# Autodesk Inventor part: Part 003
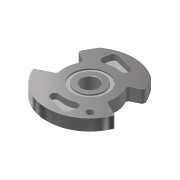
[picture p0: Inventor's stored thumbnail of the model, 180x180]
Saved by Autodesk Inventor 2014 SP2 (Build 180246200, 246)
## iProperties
Created: 2015-03
Part Number: Part 003
Material: Steel
Document SubType Name: Modeling
Designer: SFC
Density: 7.85 g/cm^3
Appearance: Steel
Mass: 161.859 g
Surface Area: 78.7289 cm^2
Volume: 20.6189 cm^3
Author: SFC
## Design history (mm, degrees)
sketch "Sketch1"
  geometry: L1 (-19, 25.997)-(-23.665, 17.917); L2 (-22.596, 14.42)-(-17.512, 11.94); L3 (19, 25.997)-(23.665, 17.917); L4 (22.596, 14.42)-(17.512, 11.94); L5 (0, -45.08)-(0, 45.08) reference; L6 (-29.187, -11.224)-(-19.581, -6.539); L7 (19.581, -6.539)-(29.187, -11.224); L8 (-49.656, 0)-(50.759, 0) reference; A1 r 32.2 centre (0, 0) between (-32.2, 0) and (-30.025, -11.633); A2 r 19 centre (0, 0) between (-16.637, 9.176) and (-18.509, -4.29); A3 r 2.5 centre (-21.5, 16.667) between (-23.665, 17.917) and (-22.596, 14.42); A4 r 2.5 centre (21.5, 16.667) between (22.596, 14.42) and (23.665, 17.917); A5 r 19 centre (0, 0) between (0, 19) and (-15.516, 10.967); A6 r 19 centre (0, 0) between (-18.089, -5.811) and (18.089, -5.811); A7 r 19 centre (0, 0) between (18.509, -4.29) and (16.637, 9.176); A8 r 19 centre (0, 0) between (15.516, 10.967) and (0, 19); A9 r 32.2 centre (0, 0) between (-19, 25.997) and (-32.2, 0); A10 r 32.2 centre (0, 0) between (-29.67, -12.511) and (29.67, -12.511); A11 r 32.2 centre (0, 0) between (30.025, -11.633) and (19, 25.997); A12 r 32.2 centre (0, 0) between (19, 25.997) and (-19, 25.997); A13 r 2 centre (-18.388, 10.142) between (-16.637, 9.176) and (-17.512, 11.94); A14 r 2 centre (-20.458, -4.741) between (-19.581, -6.539) and (-18.509, -4.29); A15 r 2 centre (18.388, 10.142) between (17.512, 11.94) and (16.637, 9.176); A16 r 2 centre (20.458, -4.741) between (18.509, -4.29) and (19.581, -6.539); A17 r 1 centre (-28.749, -12.123) between (-29.187, -11.224) and (-29.67, -12.511); A18 r 1 centre (28.749, -12.123) between (29.67, -12.511) and (29.187, -11.224); 1 further point
  constraints: 48 point on circle, 18 centre point, 16 tangent, 12 end point, 8 point on line, 5 equal radius, 2 coincident, 3 other
  dimensions: "d0" = 64.4 diameter of A1; "d1" = 38 diameter of A2; "d2" = 52 deg angle of L6 L2; "d3" = 26 deg angle of L6 L8; "d4" = 30 deg angle of L5 L1; "d5" = 2.5 radius of A3; "d6" = 2 radius of A13; "d7" = 1 radius of A17; "d8" = 48 dimension on A4 A3
extrude "Extrusion1" new body sketch "Sketch1" distance "d13" = 9.1; taper "d14" = 0 deg
sketch "Sketch2"
  geometry: L1 (10.659, -25.326)-(11.454, -20.813); L2 (-41.648, 0)-(41.648, 0) reference; L3 (0, -45.08)-(0, 45.08) reference; L4 (-5.276, -24.433)-(6.928, -27.703); A1 r 19 centre (0, 0) between (18.509, -4.29) and (16.637, 9.176) reference; A2 r 32.2 centre (0, 0) between (19, 25.997) and (-19, 25.997) reference; A3 r 19 centre (0, 0) between (-3.886, -18.598) and (7.341, -17.525); A4 r 3 centre (8.5, -20.292) between (11.454, -20.813) and (7.341, -17.525); A5 r 3 centre (-4.5, -21.535) between (-3.886, -18.598) and (-5.276, -24.433); A6 r 3 centre (7.704, -24.805) between (6.928, -27.703) and (10.659, -25.326); 1 further point
  constraints: 9 point on circle, 6 tangent, 4 centre point, 4 end point, 2 equal radius, 1 coincident, 1 point on line
  dimensions: "d15" = 3 radius of A4; "d16" = 10 deg angle of L3 L1; "d17" = 11.5 dimension on A4 L3; "d18" = 7.5 dimension on A5 L3 (computed from d17); "d19" = 15 deg angle of L2 L4; "d20" = 3 radius of A6
extrude "Extrusion2" cut sketch "Sketch2" distance "d21" = 4.3; taper "d22" = 0 deg
fillet "Fillet1" dims "d23" = 0.2
pattern_circular "Circular Pattern1" dims angle "d25" = 360 deg
sketch "Sketch3"
  geometry: C1 r 12.9 at (0, 0); C2 r 10.4 at (0, 0); A1 r 32.2 centre (0, 0) between (19, 25.997) and (-19, 25.997) reference
  constraints: 2 centre point, 2 coincident
  dimensions: "d27" = 25.8 diameter of C1; "d28" = 20.8 diameter of C2
extrude "Extrusion3" cut sketch "Sketch3" distance "d29" = 1; taper "d30" = 0 deg
fillet "Fillet2" dims "d31" = 0.2
workplane "Work Plane1"
sketch "Sketch4"
  geometry: L1 (11, 22.602)-(11, 17.659); L2 (-11, 22.602)-(-11, 17.659); L3 (11, 17.299)-(11, -17.299); L4 (11, -17.659)-(11, -22.602); L5 (-11, -17.659)-(-11, -22.602); L6 (-11, 17.299)-(-11, -17.299); A1 r 25.25 centre (0, 0) between (10.886, 22.783) and (-10.886, 22.783); A2 r 20.5 centre (0, 0) between (10.696, 17.489) and (-10.696, 17.489); A3 r 25.25 centre (0, 0) between (11, -22.728) and (11, 22.728); A4 r 25.25 centre (0, 0) between (-11, 22.728) and (-11, -22.728); A5 r 25.25 centre (0, 0) between (-10.886, -22.783) and (10.886, -22.783); A6 r 20.5 centre (0, 0) between (11, -17.299) and (11, 17.299); A7 r 20.5 centre (0, 0) between (-11, 17.299) and (-11, -17.299); A8 r 20.5 centre (0, 0) between (-10.696, -17.489) and (10.696, -17.489); A9 r 0.2 centre (10.8, 22.602) between (11, 22.602) and (10.886, 22.783); A10 r 0.2 centre (10.8, 17.659) between (10.696, 17.489) and (11, 17.659); A11 r 0.2 centre (-10.8, 22.602) between (-10.886, 22.783) and (-11, 22.602); A12 r 0.2 centre (-10.8, 17.659) between (-11, 17.659) and (-10.696, 17.489); A13 r 0.2 centre (10.8, -17.659) between (11, -17.659) and (10.696, -17.489); A14 r 0.2 centre (10.8, -22.602) between (10.886, -22.783) and (11, -22.602); A15 r 0.2 centre (-10.8, -17.659) between (-10.696, -17.489) and (-11, -17.659); A16 r 0.2 centre (-10.8, -22.602) between (-11, -22.602) and (-10.886, -22.783); 2 further points
  constraints: 42 point on circle, 16 centre point, 16 tangent, 12 end point, 9 parallel, 9 point on line, 7 equal radius, 3 vertical, 2 coincident, 1 vertical alignment
  dimensions: "d33" = 50.5 diameter of A1; "d34" = 41 diameter of A2; "d35" = 22 distance between parallel lines of L2 L1; "d36" = 0.2 radius of A9
extrude "Extrusion4" cut sketch "Sketch4" stored distance "d37" = 1; taper "d38" = 60 deg
hole "Hole1" diameter "d41" = 12.6; stored, may be unused: countersink angle "d45" = 90 deg, drill point angle "d47" = 118 deg; dims "d39" = 10, "d40" = 10, "d42" = 6, "d43" = 4, "d44" = 2, "d46" = 8
chamfer "Chamfer1" distance "d48" = 0.3; stored, may be unused: second distance "d49" = 2, angle "d50" = 45 deg
chamfer "Chamfer2" distance "d51" = 0.2; stored, may be unused: second distance "d52" = 2, angle "d53" = 45 deg
sketch "Sketch5"
  geometry: L1 (18.738, -18.738)-(0, 0); L2 (0, -45.08)-(0, 45.08) reference; C1 r 12.9 at (0, 0) reference
  constraints: 2 end point
  dimensions: "d54" = 45 deg angle of L1 L2; "d55" = 26.5 distance of L1.start L1.end
hole "Hole2" sketch "Sketch5" at (18.738, -18.738) diameter "d56" = 5; stored, may be unused: countersink angle "d60" = 90 deg, drill point angle "d62" = 118 deg; dims "d57" = 6, "d58" = 4, "d59" = 2, "d61" = 8
sketch "Sketch6"
  geometry: L1 (-12.511, 0)-(-32.2, 0) reference; L2 (-31.2, 0)-(-32.2, 1); L3 (-32.2, 1)-(-32.2, 0); L4 (-32.2, 0)-(-31.2, 0); L5 (0, -1.82)-(0, 10.92) reference; 1 further point
  constraints: 6 end point, 1 horizontal, 1 perpendicular
  dimensions: "d63" = 45 deg angle of L1 L2; "d64" = 1 distance of L2.end L1.end
revolve "Revolution1" sketch "Sketch6" stored, may be unused: angle "d65" = 90 deg
body "Solid1"
other parameters: "d32" = 0.7
